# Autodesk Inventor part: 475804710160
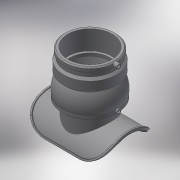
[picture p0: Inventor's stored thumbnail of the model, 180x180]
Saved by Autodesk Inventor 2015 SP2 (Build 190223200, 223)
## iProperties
Created: 2017-08
Part Number: 475804710160
Material: Generic
Description: PLASSON WASTEWATER SADDLE 560-710x160 EF ADJUSTABLE INLET
Document SubType Name: Modeling
Designer: Кирилл
Density: 1 g/cm^3
Appearance: Default
Author: Кирилл
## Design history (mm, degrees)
derived "475804.ipt"
feature "Solid1::475804.ipt"
feature "Solid2::475804.ipt"
tag "TaggingFeature1"
body "Solid1"
body "Solid2"
other parameters: "d0" = 161.6, "d3" = 45 deg, "d4" = 184, "d5" = 176, "d6" = 142.208, "d7" = 129.28, "d8" = 144, "d13" = 45 deg, "d15" = 135 deg, "d17" = 192, "d18" = 45 deg, "d19" = 80.8, "d22" = 4, "d23" = 16.16, "d25" = 45 deg, "d26" = 15 deg, "d27" = 262.6, "d28" = 136, "d29" = 156.8, "d32" = 202, "d37" = 0, "d38" = 277, "d39" = 138.5, "d40" = 731.3, "d42" = 0, "d52" = 110.8, "d53" = 8.31, "d55" = 1.108, "d56" = 224, "d57" = 0, "d58" = 105, "d59" = 15, "d61" = 5 deg, "d62" = 15, "d65" = 4, "d66" = 4, "d67" = 14, "d68" = 0, "d69" = 3, "d70" = 0, "B_" = 277, "H_" = 202, "A_" = 105, "d21" = 4
